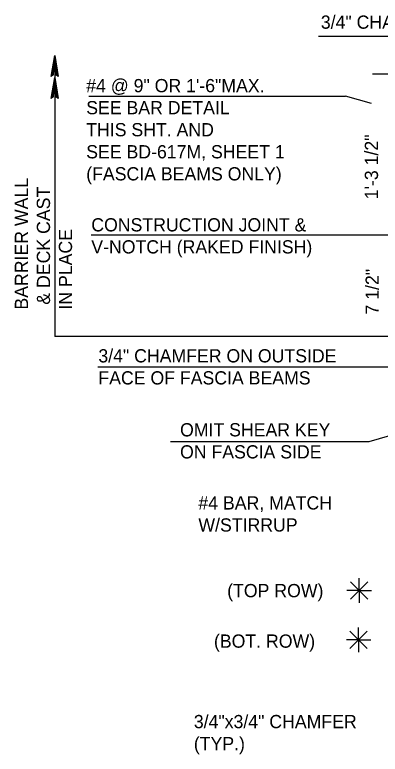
# Model space of a CAD drawing. Extents: x 642009 to 642864, y 298232 to 300014.
# Drawn here: x 642460.7 to 642543.6, y 298559.8 to 298727.5 of the extents above; entities that cross this region are included whole.
import ezdxf

# ---------------------------------------------------------------- set-up
doc = ezdxf.new("R2010")
doc.units = 0
for name, color, linetype in [('1', 7, 'Continuous'), ('2', 7, 'Continuous'), ('22', 7, 'Continuous')]:
    doc.layers.add(name, color=color, linetype=linetype)

msp = doc.modelspace()

# ---------------------------------------------------------------- linework, layer by layer
at = {"layer": '1'}
for p, q in [((642469.71, 298718.29), (642469.71, 298654.55)), ((642567.92, 298714.11), (642541.81, 298714.11)), ((642567.82, 298677.54), (642477.97, 298677.54)), ((642565.07, 298654.55), (642469.71, 298654.55)), ((642538.78, 298596.99), (642536.81, 298598.96)), ((642538.78, 298596.99), (642538.78, 298599.78)), ((642538.78, 298596.99), (642540.75, 298598.96)), ((642538.78, 298596.99), (642535.99, 298596.99)), ((642538.78, 298596.99), (642536.81, 298595.02)), ((642538.78, 298596.99), (642538.78, 298594.2)), ((642538.78, 298596.99), (642540.75, 298595.02)), ((642538.78, 298596.99), (642541.57, 298596.99)), ((642538.67, 298585.76), (642536.7, 298587.73)), ((642538.67, 298585.76), (642538.67, 298588.55)), ((642538.67, 298585.76), (642540.64, 298587.73)), ((642538.67, 298585.76), (642535.88, 298585.76)), ((642538.67, 298585.76), (642536.7, 298583.79)), ((642538.67, 298585.76), (642541.45, 298585.76)), ((642538.67, 298585.76), (642540.64, 298583.79)), ((642538.67, 298585.76), (642538.67, 298582.97))]:
    msp.add_line(p, q, dxfattribs=at)
for points in [[(642469.14, 298713.75), (642469.47, 298713.92), (642469.71, 298718.29), (642469.14, 298713.75), (642468.94, 298713.51), (642469.71, 298718.29), (642469.93, 298713.92), (642470.25, 298713.76), (642469.71, 298718.29), (642470.47, 298713.51), (642470.25, 298713.76)], [(642469.14, 298708.76), (642469.47, 298708.93), (642469.71, 298713.3), (642469.14, 298708.76), (642468.94, 298708.53), (642469.71, 298713.3), (642469.93, 298708.94), (642470.25, 298708.78), (642469.71, 298713.3), (642470.47, 298708.53), (642470.25, 298708.78)]]:
    msp.add_lwpolyline(points, dxfattribs=at)
at = {"layer": '22'}
for p, q in [((642529.55, 298722.67), (642562.94, 298722.67)), ((642477.43, 298709.09), (642535.72, 298709.09)), ((642541.58, 298707.41), (642535.72, 298709.09)), ((642479.53, 298647.7), (642547.21, 298647.7)), ((642541.03, 298630.8), (642570.29, 298639.12)), ((642495.95, 298630.8), (642541.03, 298630.8))]:
    msp.add_line(p, q, dxfattribs=at)

# ---------------------------------------------------------------- texts
at = {"layer": '1'}
for s, p in [('1\'-3 1/2"', (642543.07, 298685.71)), ('7 1/2"', (642543.24, 298659.56))]:
    msp.add_text(s, height=3, rotation=90, dxfattribs=at).set_placement(p)
at = {"layer": '2'}
for s, p in [('#4 BAR, MATCH', (642502.31, 298615.34)), ('W/STIRRUP', (642502.31, 298610.34)), ('(TOP ROW)', (642508.84, 298595.45)), ('(BOT. ROW)', (642505.84, 298584)), ('3/4"x3/4" CHAMFER', (642501.28, 298565.75)), ('(TYP.)', (642501.28, 298560.75))]:
    msp.add_text(s, height=3, dxfattribs=at).set_placement(p)
at = {"layer": '22'}
for s, height, rotation, p in [('3/4" CHAMFER', 2.9997, 360, (642530.09, 298724.38)), ('BARRIER WALL', 2.9997, 90, (642463.65, 298660.68)), (' & DECK CAST', 2.9997, 90, (642468.65, 298660.68)), ('CONSTRUCTION JOINT &', 2.9997, 360, (642478.01, 298678.41)), ('IN PLACE', 3, 90, (642473.65, 298660.68)), ('V-NOTCH (RAKED FINISH)', 2.9997, 360, (642478.01, 298673.41)), ('3/4" CHAMFER ON OUTSIDE', 2.9997, 360, (642479.62, 298648.7)), ('FACE OF FASCIA BEAMS', 2.9997, 360, (642479.62, 298643.7)), ('OMIT SHEAR KEY', 2.9997, 360, (642498.15, 298631.92)), ('ON FASCIA SIDE', 2.9997, 360, (642498.15, 298626.92))]:
    msp.add_text(s, height=height, rotation=rotation, dxfattribs=at).set_placement(p)
for s, p in [('#4 @ 9" OR 1\'-6"MAX.', (642476.86, 298709.98)), ('SEE BAR DETAIL', (642476.86, 298704.98)), ('THIS SHT. AND', (642476.86, 298699.98)), ('SEE BD-617M, SHEET 1', (642476.86, 298694.98)), ('(FASCIA BEAMS ONLY)', (642476.86, 298689.98))]:
    msp.add_text(s, height=2.9997, dxfattribs=at).set_placement(p)

doc.saveas('drawing.dxf')
